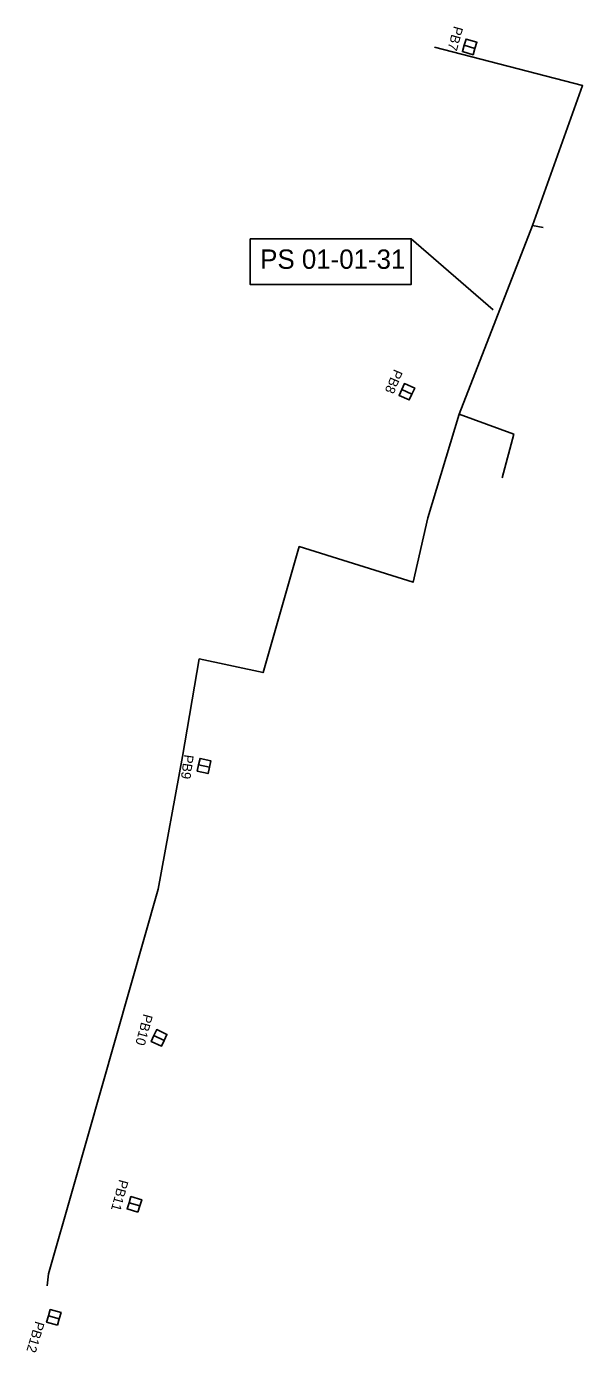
# Model space of a CAD drawing. Extents: x -526854 to -526702, y -1078757 to -1078333.
# Drawn here: x -526811.3 to -526753.8, y -1078756.8 to -1078619.7 of the extents above; entities that cross this region are included whole.
import ezdxf

# ---------------------------------------------------------------- set-up
doc = ezdxf.new("R2010")
doc.units = 0
for name, color, linetype in [('PS01', 7, 'Continuous'), ('PS010131', 7, 'Continuous'), ('PS010131 nová kabelizace', 7, 'Continuous'), ('Vrstva 12', 7, 'Continuous')]:
    doc.layers.add(name, color=color, linetype=linetype)

msp = doc.modelspace()

# ---------------------------------------------------------------- linework, layer by layer
at = {"layer": 'PS01'}
for points in [[(-526766.04, -1078621.63), (-526765.84, -1078620.98), (-526764.73, -1078621.32), (-526764.93, -1078621.97)], [(-526764.93, -1078621.97), (-526764.73, -1078621.32), (-526765.84, -1078620.98), (-526766.04, -1078621.63)], [(-526765.12, -1078622.61), (-526764.93, -1078621.97), (-526766.04, -1078621.63), (-526766.23, -1078622.28)], [(-526766.23, -1078622.28), (-526766.04, -1078621.63), (-526764.93, -1078621.97), (-526765.12, -1078622.61)], [(-526765.12, -1078622.61), (-526764.93, -1078621.97), (-526766.04, -1078621.63), (-526766.23, -1078622.28)], [(-526771.44, -1078657.71), (-526771.16, -1078657.09), (-526772.22, -1078656.62), (-526772.5, -1078657.23)], [(-526771.72, -1078658.32), (-526771.44, -1078657.71), (-526772.5, -1078657.23), (-526772.77, -1078657.85)], [(-526772.77, -1078657.84), (-526772.5, -1078657.23), (-526771.44, -1078657.71), (-526771.72, -1078658.32)], [(-526771.72, -1078658.32), (-526771.44, -1078657.71), (-526772.5, -1078657.23), (-526772.77, -1078657.85)], [(-526792.38, -1078696.31), (-526792.23, -1078695.66), (-526793.36, -1078695.4), (-526793.51, -1078696.06)], [(-526792.53, -1078696.97), (-526792.38, -1078696.31), (-526793.51, -1078696.06), (-526793.66, -1078696.71)], [(-526793.66, -1078696.71), (-526793.51, -1078696.06), (-526792.38, -1078696.31), (-526792.53, -1078696.97)], [(-526792.53, -1078696.97), (-526792.38, -1078696.31), (-526793.51, -1078696.06), (-526793.66, -1078696.71)], [(-526799.79, -1078742.34), (-526799.6, -1078741.69), (-526800.71, -1078741.35), (-526800.91, -1078742)], [(-526800.71, -1078741.35), (-526800.52, -1078740.71), (-526799.4, -1078741.04), (-526799.6, -1078741.69)], [(-526799.6, -1078741.69), (-526799.4, -1078741.04), (-526800.52, -1078740.71), (-526800.71, -1078741.35)], [(-526809.04, -1078753.04), (-526808.85, -1078752.4), (-526807.74, -1078752.72), (-526807.93, -1078753.37)], [(-526807.93, -1078753.37), (-526807.74, -1078752.72), (-526808.85, -1078752.4), (-526809.04, -1078753.04)], [(-526808.11, -1078754.02), (-526807.93, -1078753.37), (-526809.04, -1078753.04), (-526809.23, -1078753.69)]]:
    msp.add_lwpolyline(points, close=True, dxfattribs=at)
at = {"layer": 'PS010131'}
for points in [[(-526797.36, -1078725.17), (-526797.07, -1078724.56), (-526798.13, -1078724.06), (-526798.41, -1078724.68)], [(-526798.41, -1078724.68), (-526798.13, -1078724.06), (-526797.07, -1078724.56), (-526797.36, -1078725.17)], [(-526798.13, -1078724.06), (-526797.84, -1078723.45), (-526796.79, -1078723.94), (-526797.07, -1078724.56)], [(-526797.07, -1078724.56), (-526796.79, -1078723.94), (-526797.84, -1078723.45), (-526798.13, -1078724.06)]]:
    msp.add_lwpolyline(points, close=True, dxfattribs=at)
at = {"layer": 'PS010131 nová kabelizace'}
for points in [[(-526757.87, -1078640.49), (-526758.98, -1078640.26), (-526753.8, -1078625.79), (-526769.12, -1078621.83)], [(-526758.98, -1078640.26), (-526766.56, -1078659.79), (-526769.8, -1078670.5), (-526771.32, -1078677.18), (-526783.1, -1078673.48), (-526786.84, -1078686.52), (-526793.44, -1078685.1), (-526795.18, -1078695.21), (-526795.18, -1078695.21), (-526797.69, -1078708.92), (-526806.47, -1078739.69), (-526809.03, -1078748.72), (-526809.18, -1078749.95)], [(-526762.11, -1078666.37), (-526760.91, -1078661.85), (-526766.56, -1078659.79)]]:
    msp.add_lwpolyline(points, dxfattribs=at)
at = {"layer": 'Vrstva 12'}
msp.add_line((-526771.51, -1078641.66), (-526763.04, -1078649), dxfattribs=at)
msp.add_lwpolyline([(-526788.19, -1078641.66), (-526771.51, -1078641.66), (-526771.51, -1078646.36), (-526788.19, -1078646.36)], close=True, dxfattribs=at)

# ---------------------------------------------------------------- texts
at = {"layer": 'PS01'}
for s, rotation, p in [('PB7', 254.4401, (-526767.1, -1078619.58)), ('PB8', 247.0606, (-526773.29, -1078655.06)), ('PB9', 261.9118, (-526795, -1078694.95))]:
    msp.add_text(s, height=1, rotation=rotation, dxfattribs=at).set_placement(p)
at = {"layer": 'PS010131'}
for s, rotation, p in [('PB10', 254.6683, (-526799.2, -1078721.76)), ('PB11', 254.6683, (-526801.72, -1078738.89)), ('PB12', 253.211, (-526810.39, -1078753.54))]:
    msp.add_text(s, height=1, rotation=rotation, dxfattribs=at).set_placement(p)
at = {"layer": 'Vrstva 12'}
msp.add_text('PS 01-01-31', height=2, dxfattribs=at).set_placement((-526787.14, -1078644.75))

doc.saveas('drawing.dxf')
